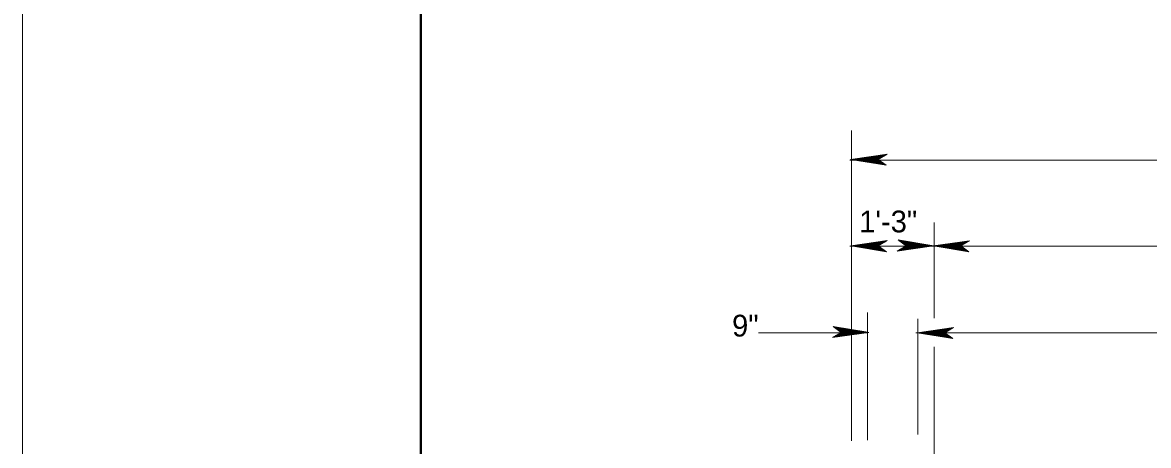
# Model space of a CAD drawing. Extents: x 144 to 252, y 360 to 425.
# Drawn here: x 143.81 to 160.77, y 400.64 to 407.01 of the extents above; entities that cross this region are included whole.
import ezdxf
from ezdxf.enums import TextEntityAlignment as Align

# ---------------------------------------------------------------- set-up
doc = ezdxf.new("R2010")
doc.units = 0
doc.header["$LTSCALE"] = 0.13
for name, color, linetype, lineweight in [('1', 7, 'Continuous', 40), ('16', 7, 'Continuous', 13), ('3', 7, 'Continuous', 13)]:
    doc.layers.add(name, color=color, linetype=linetype, lineweight=lineweight)

msp = doc.modelspace()

# ---------------------------------------------------------------- linework, layer by layer
at = {"layer": '1', "lineweight": 13}
for p, q in [((156.2978, 400.7987), (156.2978, 403.651)), ((157.2978, 401.8707), (157.2978, 402.5461)), ((156.5413, 402.3377), (154.9005, 402.3377)), ((177.3103, 402.3377), (157.2677, 402.3377)), ((157.2978, 401.3854), (157.2978, 401.8707)), ((157.2978, 400.8039), (157.2978, 401.7233)), ((156.2978, 400.7095), (156.2978, 400.944))]:
    msp.add_line(p, q, dxfattribs=at)
at = {"layer": '1'}
msp.add_lwpolyline([(250.3172, 361.9183), (250.3172, 423.9913), (149.8112, 423.9913), (149.8112, 361.9183), (230.3642, 361.9183)], dxfattribs=at)
at = {"layer": '16'}
msp.add_line((143.8112, 360.4183), (143.8112, 425.4823), dxfattribs=at)
at = {"layer": '3'}
for p, q in [((156.2978, 403.4373), (156.2978, 405.383)), ((156.2728, 404.9348), (180.2736, 404.9348)), ((156.8343, 405.0269), (156.2856, 404.9492)), ((156.2856, 404.9492), (156.8233, 404.8599)), ((156.701, 404.9492), (156.2856, 404.9492)), ((156.8283, 405.0234), (156.3, 404.9485)), ((156.3, 404.9485), (156.82, 404.8622)), ((156.8248, 405.0214), (156.3108, 404.9485)), ((156.3108, 404.9485), (156.8167, 404.8646)), ((156.8202, 405.0188), (156.3252, 404.9485)), ((156.3252, 404.9485), (156.8125, 404.8678)), ((156.8162, 405.0163), (156.338, 404.9485)), ((156.8162, 405.0163), (156.338, 404.9485)), ((156.338, 404.9485), (156.8088, 404.8704)), ((156.8125, 405.0142), (156.3493, 404.9485)), ((156.3493, 404.9485), (156.8054, 404.8728)), ((156.8079, 405.0115), (156.3637, 404.9485)), ((156.3637, 404.9485), (156.8012, 404.876)), ((156.8038, 405.0091), (156.3765, 404.9485)), ((156.3765, 404.9485), (156.7974, 404.8787)), ((156.7994, 405.0066), (156.3903, 404.9485)), ((156.3903, 404.9485), (156.7933, 404.8817)), ((156.795, 405.004), (156.4041, 404.9485)), ((156.4041, 404.9485), (156.7892, 404.8847)), ((156.7908, 405.0015), (156.4173, 404.9485)), ((156.4173, 404.9485), (156.7853, 404.8875)), ((156.7862, 404.9988), (156.4313, 404.9485)), ((156.4313, 404.9485), (156.7812, 404.8905)), ((156.7823, 404.9966), (156.4438, 404.9485)), ((156.4438, 404.9485), (156.7775, 404.8932)), ((156.7785, 404.9943), (156.4553, 404.9485)), ((156.4553, 404.9485), (156.7741, 404.8957)), ((156.7735, 404.9915), (156.4709, 404.9485)), ((156.4709, 404.9485), (156.7695, 404.899)), ((156.7691, 404.9888), (156.4847, 404.9485)), ((156.4847, 404.9485), (156.7654, 404.902)), ((156.7619, 404.9847), (156.5027, 404.948)), ((156.5027, 404.948), (156.7612, 404.9051)), ((156.7651, 404.9866), (156.5043, 404.9496)), ((156.7575, 404.9821), (156.5167, 404.948)), ((156.5167, 404.948), (156.757, 404.9081)), ((156.7533, 404.9796), (156.5298, 404.948)), ((156.5298, 404.948), (156.7532, 404.9109)), ((156.7517, 404.9787), (156.5389, 404.9485)), ((156.5389, 404.9485), (156.7494, 404.9137)), ((156.7478, 404.9765), (156.5509, 404.9485)), ((156.5509, 404.9485), (156.7458, 404.9162)), ((156.7434, 404.9738), (156.5648, 404.9485)), ((156.5648, 404.9485), (156.7417, 404.9192)), ((156.7384, 404.971), (156.5804, 404.9485)), ((156.5804, 404.9485), (156.7371, 404.9225)), ((156.7343, 404.9686), (156.593, 404.9485)), ((156.593, 404.9485), (156.7334, 404.9253)), ((156.7301, 404.9661), (156.6062, 404.9485)), ((156.6062, 404.9485), (156.7295, 404.9281)), ((156.7262, 404.9638), (156.6182, 404.9485)), ((156.6182, 404.9485), (156.7259, 404.9307)), ((156.7216, 404.9612), (156.6327, 404.9485)), ((156.6327, 404.9485), (156.7217, 404.9337)), ((156.7172, 404.9586), (156.6466, 404.9485)), ((156.6466, 404.9485), (156.7175, 404.9367)), ((156.7131, 404.9563), (156.6592, 404.9485)), ((156.6592, 404.9485), (156.7138, 404.9395)), ((156.6725, 404.9485), (156.7099, 404.9423)), ((156.7078, 404.9532), (156.6827, 404.9496)), ((156.7052, 404.9516), (156.6839, 404.9485)), ((156.6839, 404.9485), (156.7065, 404.9447)), ((156.6941, 404.9485), (156.7035, 404.947)), ((156.7007, 404.949), (156.8343, 405.0269)), ((156.8233, 404.8599), (156.7007, 404.949)), ((156.2978, 403.4373), (156.2978, 403.9957)), ((157.5437, 403.4373), (157.5437, 403.9957)), ((156.8355, 403.7248), (156.2867, 403.6471)), ((156.8295, 403.7213), (156.3012, 403.6464)), ((156.826, 403.7193), (156.312, 403.6464)), ((156.8214, 403.7167), (156.3264, 403.6464)), ((156.8173, 403.7142), (156.3392, 403.6464)), ((156.8173, 403.7142), (156.3392, 403.6464)), ((156.8137, 403.7121), (156.3505, 403.6464)), ((156.8091, 403.7094), (156.3649, 403.6464)), ((156.805, 403.707), (156.3777, 403.6464)), ((156.8006, 403.7045), (156.3914, 403.6464)), ((156.7962, 403.7019), (156.4052, 403.6464)), ((156.7919, 403.6994), (156.4185, 403.6464)), ((156.7874, 403.6968), (156.4324, 403.6464)), ((156.7834, 403.6945), (156.445, 403.6464)), ((156.7797, 403.6923), (156.4564, 403.6464)), ((156.7019, 403.6469), (156.8355, 403.7248)), ((157.5375, 403.6453), (156.9998, 403.7346)), ((156.9998, 403.7346), (157.1223, 403.6455)), ((157.5231, 403.646), (157.0031, 403.7322)), ((157.5122, 403.646), (157.0063, 403.7299)), ((157.4978, 403.646), (157.0106, 403.7267)), ((157.4851, 403.646), (157.0143, 403.7241)), ((157.4737, 403.646), (157.0177, 403.7217)), ((157.4593, 403.646), (157.0219, 403.7185)), ((157.4466, 403.646), (157.0257, 403.7158)), ((157.4328, 403.646), (157.0298, 403.7128)), ((157.419, 403.646), (157.0338, 403.7098)), ((157.4057, 403.646), (157.0377, 403.707)), ((157.3918, 403.646), (157.0418, 403.704)), ((157.3792, 403.646), (157.0456, 403.7013)), ((157.3678, 403.646), (157.049, 403.6988)), ((157.3522, 403.646), (157.0536, 403.6955)), ((157.3383, 403.646), (157.0577, 403.6925)), ((158.0788, 403.7231), (157.5301, 403.6453)), ((158.0728, 403.7196), (157.5445, 403.6447)), ((158.0693, 403.7176), (157.5553, 403.6447)), ((158.0648, 403.7149), (157.5697, 403.6447)), ((158.0607, 403.7125), (157.5825, 403.6447)), ((158.0607, 403.7125), (157.5825, 403.6447)), ((158.057, 403.7103), (157.5938, 403.6447)), ((158.0524, 403.7077), (157.6082, 403.6447)), ((158.0483, 403.7052), (157.621, 403.6447)), ((158.0439, 403.7027), (157.6347, 403.6447)), ((158.0395, 403.7002), (157.6486, 403.6447)), ((158.0352, 403.6977), (157.6618, 403.6447)), ((158.0307, 403.695), (157.6757, 403.6447)), ((158.0267, 403.6927), (157.6883, 403.6447)), ((157.9452, 403.6452), (158.0788, 403.7231)), ((156.2738, 403.6397), (178.9784, 403.6397)), ((156.2867, 403.6471), (156.8244, 403.5578)), ((156.7022, 403.6471), (156.2867, 403.6471)), ((156.2978, 403.4373), (156.2978, 403.5417)), ((156.2978, 403.3887), (156.2978, 403.5417)), ((156.3012, 403.6464), (156.8212, 403.5602)), ((156.312, 403.6464), (156.8179, 403.5625)), ((156.3264, 403.6464), (156.8137, 403.5657)), ((156.3392, 403.6464), (156.8099, 403.5683)), ((156.3505, 403.6464), (156.8066, 403.5707)), ((156.3649, 403.6464), (156.8023, 403.5739)), ((156.3777, 403.6464), (156.7986, 403.5767)), ((156.3914, 403.6464), (156.7945, 403.5796)), ((156.4052, 403.6464), (156.7904, 403.5826)), ((156.4185, 403.6464), (156.7865, 403.5854)), ((156.4324, 403.6464), (156.7824, 403.5884)), ((156.445, 403.6464), (156.7787, 403.5911)), ((156.4564, 403.6464), (156.7752, 403.5936)), ((156.7747, 403.6894), (156.4721, 403.6464)), ((156.4721, 403.6464), (156.7707, 403.5969)), ((156.7703, 403.6867), (156.4859, 403.6464)), ((156.4859, 403.6464), (156.7666, 403.5999)), ((156.7631, 403.6826), (156.5039, 403.6459)), ((156.5039, 403.6459), (156.7623, 403.603)), ((156.7662, 403.6845), (156.5055, 403.6475)), ((156.7587, 403.68), (156.5178, 403.6459)), ((156.5178, 403.6459), (156.7582, 403.606)), ((156.7544, 403.6775), (156.531, 403.6459)), ((156.531, 403.6459), (156.7543, 403.6088)), ((156.7529, 403.6767), (156.5401, 403.6464)), ((156.5401, 403.6464), (156.7506, 403.6116)), ((156.749, 403.6744), (156.5521, 403.6464)), ((156.5521, 403.6464), (156.747, 403.6142)), ((156.7446, 403.6717), (156.5659, 403.6464)), ((156.5659, 403.6464), (156.7429, 403.6172)), ((156.7396, 403.6689), (156.5816, 403.6464)), ((156.5816, 403.6464), (156.7382, 403.6204)), ((156.7355, 403.6665), (156.5942, 403.6464)), ((156.5942, 403.6464), (156.7346, 403.6232)), ((156.7312, 403.664), (156.6074, 403.6464)), ((156.6074, 403.6464), (156.7307, 403.626)), ((156.7274, 403.6617), (156.6194, 403.6464)), ((156.6194, 403.6464), (156.7271, 403.6287)), ((156.7227, 403.6591), (156.6339, 403.6464)), ((156.6339, 403.6464), (156.7228, 403.6317)), ((156.7183, 403.6565), (156.6478, 403.6464)), ((156.6478, 403.6464), (156.7187, 403.6347)), ((156.7142, 403.6542), (156.6604, 403.6464)), ((156.6604, 403.6464), (156.715, 403.6374)), ((156.6737, 403.6464), (156.7111, 403.6402)), ((156.709, 403.6511), (156.6839, 403.6475)), ((156.7063, 403.6495), (156.6851, 403.6464)), ((156.6851, 403.6464), (156.7077, 403.6427)), ((156.6952, 403.6464), (156.7047, 403.6449)), ((156.8244, 403.5578), (156.7019, 403.6469)), ((157.1223, 403.6455), (156.9887, 403.5676)), ((156.9887, 403.5676), (157.5375, 403.6453)), ((156.9947, 403.5711), (157.5231, 403.646)), ((156.9982, 403.5731), (157.5122, 403.646)), ((157.0028, 403.5757), (157.4978, 403.646)), ((157.0069, 403.5782), (157.4851, 403.646)), ((157.0069, 403.5782), (157.4851, 403.646)), ((157.0106, 403.5803), (157.4737, 403.646)), ((157.0152, 403.583), (157.4593, 403.646)), ((157.0192, 403.5854), (157.4466, 403.646)), ((157.0237, 403.5879), (157.4328, 403.646)), ((157.0281, 403.5905), (157.419, 403.646)), ((157.0323, 403.593), (157.4057, 403.646)), ((157.0368, 403.5957), (157.3918, 403.646)), ((157.0408, 403.5979), (157.3792, 403.646)), ((157.0446, 403.6002), (157.3678, 403.646)), ((157.0496, 403.603), (157.3522, 403.646)), ((157.054, 403.6057), (157.3383, 403.646)), ((157.058, 403.6079), (157.3187, 403.6449)), ((157.0612, 403.6098), (157.3203, 403.6465)), ((157.3203, 403.6465), (157.0619, 403.6894)), ((157.0656, 403.6124), (157.3064, 403.6465)), ((157.3064, 403.6465), (157.0661, 403.6864)), ((157.0698, 403.6149), (157.2933, 403.6465)), ((157.2933, 403.6465), (157.0699, 403.6836)), ((157.0713, 403.6157), (157.2842, 403.646)), ((157.2842, 403.646), (157.0737, 403.6808)), ((157.0752, 403.618), (157.2722, 403.646)), ((157.2722, 403.646), (157.0772, 403.6782)), ((157.0797, 403.6207), (157.2583, 403.646)), ((157.2583, 403.646), (157.0813, 403.6753)), ((157.0847, 403.6235), (157.2427, 403.646)), ((157.2427, 403.646), (157.086, 403.672)), ((157.0888, 403.6259), (157.2301, 403.646)), ((157.2301, 403.646), (157.0897, 403.6692)), ((157.093, 403.6284), (157.2168, 403.646)), ((157.2168, 403.646), (157.0936, 403.6664)), ((157.0968, 403.6307), (157.2048, 403.646)), ((157.2048, 403.646), (157.0972, 403.6637)), ((157.1903, 403.646), (157.1014, 403.6608)), ((157.1015, 403.6333), (157.1903, 403.646)), ((157.1765, 403.646), (157.1056, 403.6577)), ((157.1059, 403.6359), (157.1765, 403.646)), ((157.1638, 403.646), (157.1093, 403.655)), ((157.11, 403.6382), (157.1638, 403.646)), ((157.1506, 403.646), (157.1132, 403.6522)), ((157.1153, 403.6413), (157.1403, 403.6449)), ((157.1392, 403.646), (157.1166, 403.6497)), ((157.1179, 403.6429), (157.1392, 403.646)), ((157.129, 403.646), (157.1196, 403.6475)), ((157.1221, 403.6453), (157.5375, 403.6453)), ((157.5301, 403.6453), (158.0677, 403.5561)), ((157.9455, 403.6453), (157.5301, 403.6453)), ((157.5437, 402.5589), (157.5437, 403.5417)), ((157.5445, 403.6447), (158.0645, 403.5584)), ((157.5553, 403.6447), (158.0613, 403.5607)), ((157.5697, 403.6447), (158.057, 403.5639)), ((157.5825, 403.6447), (158.0532, 403.5666)), ((157.5938, 403.6447), (158.0499, 403.569)), ((157.6082, 403.6447), (158.0457, 403.5722)), ((157.621, 403.6447), (158.0419, 403.5749)), ((157.6347, 403.6447), (158.0378, 403.5778)), ((157.6486, 403.6447), (158.0337, 403.5808)), ((157.6618, 403.6447), (158.0298, 403.5837)), ((157.6757, 403.6447), (158.0257, 403.5867)), ((157.6883, 403.6447), (158.022, 403.5893)), ((158.023, 403.6905), (157.6997, 403.6447)), ((157.6997, 403.6447), (158.0186, 403.5918)), ((158.018, 403.6877), (157.7154, 403.6447)), ((157.7154, 403.6447), (158.014, 403.5952)), ((158.0136, 403.685), (157.7293, 403.6447)), ((157.7293, 403.6447), (158.0099, 403.5982)), ((158.0064, 403.6808), (157.7473, 403.6442)), ((157.7473, 403.6442), (158.0057, 403.6012)), ((158.0096, 403.6827), (157.7488, 403.6457)), ((158.002, 403.6782), (157.7612, 403.6442)), ((157.7612, 403.6442), (158.0015, 403.6042)), ((157.9977, 403.6757), (157.7743, 403.6442)), ((157.7743, 403.6442), (157.9977, 403.6071)), ((157.9963, 403.6749), (157.7834, 403.6447)), ((157.7834, 403.6447), (157.9939, 403.6098)), ((157.9923, 403.6727), (157.7954, 403.6447)), ((157.7954, 403.6447), (157.9903, 403.6124)), ((157.9879, 403.67), (157.8092, 403.6447)), ((157.8092, 403.6447), (157.9862, 403.6154)), ((157.9829, 403.6672), (157.8249, 403.6447)), ((157.8249, 403.6447), (157.9816, 403.6187)), ((157.9788, 403.6647), (157.8375, 403.6447)), ((157.8375, 403.6447), (157.9779, 403.6214)), ((157.9746, 403.6622), (157.8508, 403.6447)), ((157.8508, 403.6447), (157.974, 403.6242)), ((157.9707, 403.66), (157.8628, 403.6447)), ((157.8628, 403.6447), (157.9704, 403.6269)), ((157.9661, 403.6573), (157.8773, 403.6447)), ((157.8773, 403.6447), (157.9662, 403.6299)), ((157.9617, 403.6547), (157.8911, 403.6447)), ((157.8911, 403.6447), (157.962, 403.6329)), ((157.9576, 403.6524), (157.9038, 403.6447)), ((157.9038, 403.6447), (157.9583, 403.6357)), ((157.917, 403.6447), (157.9544, 403.6385)), ((157.9523, 403.6493), (157.9272, 403.6457)), ((157.9497, 403.6477), (157.9284, 403.6447)), ((157.9284, 403.6447), (157.951, 403.6409)), ((157.9386, 403.6447), (157.948, 403.6432)), ((158.0677, 403.5561), (157.9452, 403.6452)), ((156.5418, 400.7174), (156.5418, 402.6439)), ((156.1445, 402.3434), (156.0109, 402.2655)), ((156.0109, 402.2655), (156.5597, 402.3433)), ((156.0169, 402.269), (156.5452, 402.3439)), ((156.0204, 402.271), (156.5344, 402.3439)), ((156.5597, 402.3433), (156.022, 402.4325)), ((156.022, 402.4325), (156.1445, 402.3434)), ((156.025, 402.2737), (156.52, 402.3439)), ((156.5452, 402.3439), (156.0252, 402.4302)), ((156.5344, 402.3439), (156.0285, 402.4278)), ((156.0291, 402.2761), (156.5072, 402.3439)), ((156.0291, 402.2761), (156.5072, 402.3439)), ((156.52, 402.3439), (156.0327, 402.4247)), ((156.0327, 402.2783), (156.4959, 402.3439)), ((156.5072, 402.3439), (156.0365, 402.422)), ((156.0373, 402.2809), (156.4815, 402.3439)), ((156.4959, 402.3439), (156.0398, 402.4196)), ((156.0414, 402.2833), (156.4688, 402.3439)), ((156.4815, 402.3439), (156.0441, 402.4164)), ((156.0458, 402.2858), (156.455, 402.3439)), ((156.4688, 402.3439), (156.0478, 402.4137)), ((156.0503, 402.2884), (156.4412, 402.3439)), ((156.455, 402.3439), (156.0519, 402.4108)), ((156.0545, 402.2909), (156.4279, 402.3439)), ((156.4412, 402.3439), (156.056, 402.4077)), ((156.059, 402.2936), (156.414, 402.3439)), ((156.4279, 402.3439), (156.0599, 402.4049)), ((156.063, 402.2958), (156.4014, 402.3439)), ((156.414, 402.3439), (156.064, 402.4019)), ((156.0667, 402.2981), (156.39, 402.3439)), ((156.4014, 402.3439), (156.0677, 402.3992)), ((156.39, 402.3439), (156.0712, 402.3967)), ((156.0718, 402.3009), (156.3743, 402.3439)), ((156.3743, 402.3439), (156.0757, 402.3934)), ((156.0762, 402.3036), (156.3605, 402.3439)), ((156.3605, 402.3439), (156.0798, 402.3904)), ((156.0802, 402.3058), (156.3409, 402.3428)), ((156.0833, 402.3077), (156.3425, 402.3444)), ((156.3425, 402.3444), (156.0841, 402.3873)), ((156.0877, 402.3103), (156.3286, 402.3444)), ((156.3286, 402.3444), (156.0882, 402.3843)), ((156.092, 402.3128), (156.3154, 402.3444)), ((156.3154, 402.3444), (156.0921, 402.3815)), ((156.0935, 402.3137), (156.3063, 402.3439)), ((156.3063, 402.3439), (156.0958, 402.3787)), ((156.0974, 402.3159), (156.2943, 402.3439)), ((156.2943, 402.3439), (156.0994, 402.3762)), ((156.1018, 402.3186), (156.2805, 402.3439)), ((156.2805, 402.3439), (156.1035, 402.3732)), ((156.1068, 402.3214), (156.2648, 402.3439)), ((156.2648, 402.3439), (156.1082, 402.3699)), ((156.1109, 402.3238), (156.2523, 402.3439)), ((156.2523, 402.3439), (156.1118, 402.3672)), ((156.1152, 402.3263), (156.239, 402.3439)), ((156.239, 402.3439), (156.1157, 402.3643)), ((156.119, 402.3286), (156.227, 402.3439)), ((156.227, 402.3439), (156.1193, 402.3617)), ((156.2125, 402.3439), (156.1236, 402.3587)), ((156.1237, 402.3313), (156.2125, 402.3439)), ((156.1987, 402.3439), (156.1277, 402.3557)), ((156.1281, 402.3338), (156.1987, 402.3439)), ((156.186, 402.3439), (156.1314, 402.3529)), ((156.1322, 402.3362), (156.186, 402.3439)), ((156.1728, 402.3439), (156.1353, 402.3501)), ((156.1374, 402.3392), (156.1625, 402.3428)), ((156.1613, 402.3439), (156.1387, 402.3477)), ((156.1401, 402.3408), (156.1613, 402.3439)), ((156.1512, 402.3439), (156.1418, 402.3454)), ((156.1442, 402.3433), (156.5597, 402.3433)), ((157.8367, 402.4157), (157.288, 402.3379)), ((157.288, 402.3379), (157.8257, 402.2487)), ((157.7034, 402.3379), (157.288, 402.3379)), ((157.8307, 402.4122), (157.3024, 402.3372)), ((157.3024, 402.3372), (157.8224, 402.251)), ((157.8272, 402.4102), (157.3132, 402.3372)), ((157.3132, 402.3372), (157.8192, 402.2533)), ((157.8227, 402.4075), (157.3277, 402.3372)), ((157.3277, 402.3372), (157.8149, 402.2565)), ((157.8186, 402.4051), (157.3404, 402.3372)), ((157.8186, 402.4051), (157.3404, 402.3372)), ((157.3404, 402.3372), (157.8112, 402.2592)), ((157.8149, 402.4029), (157.3517, 402.3372)), ((157.3517, 402.3372), (157.8078, 402.2616)), ((157.8103, 402.4002), (157.3662, 402.3372)), ((157.3662, 402.3372), (157.8036, 402.2647)), ((157.8063, 402.3978), (157.3789, 402.3372)), ((157.3789, 402.3372), (157.7998, 402.2675)), ((157.8018, 402.3953), (157.3927, 402.3372)), ((157.3927, 402.3372), (157.7957, 402.2704)), ((157.7974, 402.3927), (157.4065, 402.3372)), ((157.4065, 402.3372), (157.7917, 402.2734)), ((157.7932, 402.3902), (157.4197, 402.3372)), ((157.4197, 402.3372), (157.7877, 402.2763)), ((157.7887, 402.3876), (157.4337, 402.3372)), ((157.4337, 402.3372), (157.7837, 402.2792)), ((157.7847, 402.3853), (157.4462, 402.3372)), ((157.4462, 402.3372), (157.7799, 402.2819)), ((157.7809, 402.3831), (157.4577, 402.3372)), ((157.4577, 402.3372), (157.7765, 402.2844)), ((157.7759, 402.3802), (157.4733, 402.3372)), ((157.4733, 402.3372), (157.7719, 402.2877)), ((157.7715, 402.3776), (157.4872, 402.3372)), ((157.4872, 402.3372), (157.7678, 402.2908)), ((157.7643, 402.3734), (157.5052, 402.3367)), ((157.5052, 402.3367), (157.7636, 402.2938)), ((157.7675, 402.3753), (157.5067, 402.3383)), ((157.7599, 402.3708), (157.5191, 402.3367)), ((157.5191, 402.3367), (157.7594, 402.2968)), ((157.7557, 402.3683), (157.5323, 402.3367)), ((157.5323, 402.3367), (157.7556, 402.2997)), ((157.7542, 402.3675), (157.5413, 402.3372)), ((157.5413, 402.3372), (157.7518, 402.3024)), ((157.7502, 402.3653), (157.5533, 402.3372)), ((157.5533, 402.3372), (157.7482, 402.305)), ((157.7458, 402.3626), (157.5672, 402.3372)), ((157.5672, 402.3372), (157.7442, 402.308)), ((157.7408, 402.3597), (157.5828, 402.3372)), ((157.5828, 402.3372), (157.7395, 402.3112)), ((157.7368, 402.3573), (157.5954, 402.3372)), ((157.5954, 402.3372), (157.7358, 402.314)), ((157.7325, 402.3548), (157.6087, 402.3372)), ((157.6087, 402.3372), (157.7319, 402.3168)), ((157.7287, 402.3526), (157.6207, 402.3372)), ((157.6207, 402.3372), (157.7283, 402.3195)), ((157.724, 402.3499), (157.6352, 402.3372)), ((157.6352, 402.3372), (157.7241, 402.3225)), ((157.7196, 402.3473), (157.649, 402.3372)), ((157.649, 402.3372), (157.7199, 402.3255)), ((157.7155, 402.345), (157.6617, 402.3372)), ((157.6617, 402.3372), (157.7163, 402.3282)), ((157.6749, 402.3372), (157.7123, 402.3311)), ((157.7103, 402.3419), (157.6852, 402.3383)), ((157.7076, 402.3403), (157.6863, 402.3372)), ((157.6863, 402.3372), (157.7089, 402.3335)), ((157.6965, 402.3372), (157.7059, 402.3357)), ((157.7032, 402.3377), (157.8367, 402.4157)), ((157.8257, 402.2487), (157.7032, 402.3377)), ((156.2978, 401.2439), (156.2978, 402.2423)), ((156.2978, 401.2439), (156.2978, 402.202)), ((157.5437, 401.858), (157.5437, 402.1256)), ((157.5437, 401.4561), (157.5437, 401.858)), ((157.5437, 399.4644), (157.5437, 401.7233)), ((156.2978, 400.7095), (156.2978, 400.944)), ((157.5437, 399.4644), (157.5437, 400.8253))]:
    msp.add_line(p, q, dxfattribs=at)

# ---------------------------------------------------------------- texts
at = {"layer": '16'}
msp.add_text('1\'-3"', height=0.3281, dxfattribs=at).set_placement((156.8524, 403.8496), align=Align.CENTER)
msp.add_text('9"', height=0.3281, dxfattribs=at).set_placement((154.5001, 402.2803))

doc.saveas('drawing.dxf')
